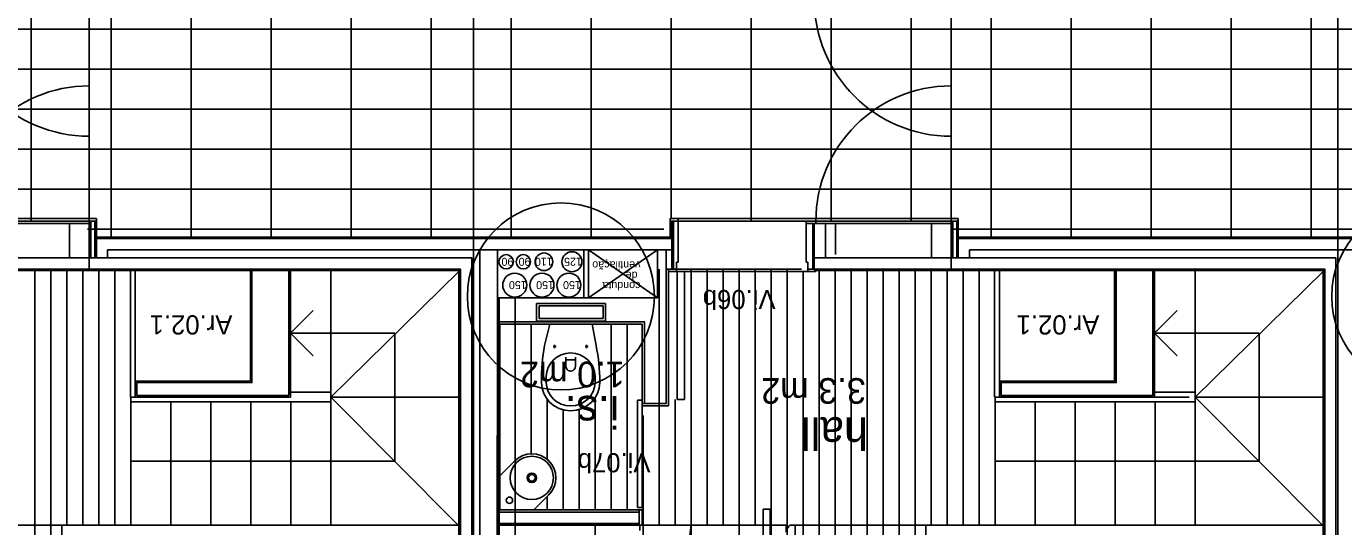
# Model space of a CAD drawing. Extents: x 1248 to 1356, y -443 to -224.
# Drawn here: x 1326.49 to 1334.72, y -242.03 to -238.91 of the extents above; entities that cross this region are included whole.
import ezdxf

# ---------------------------------------------------------------- set-up
doc = ezdxf.new("R2010")
doc.units = 0
for name, color, linetype in [('corte', 7, 'Continuous'), ('estereoctomias', 7, 'Continuous'), ('ind-pormenores', 7, 'Continuous'), ('Level 1', 7, 'Continuous'), ('Level 10', 7, 'Continuous'), ('Level 11', 7, 'Continuous'), ('Level 13', 7, 'Continuous'), ('Level 2', 7, 'Continuous'), ('Level 31', 7, 'Continuous'), ('Level 4', 7, 'Continuous'), ('Level 40', 7, 'Continuous'), ('Level 41', 7, 'Continuous'), ('Level 60', 7, 'Continuous'), ('mob-fixo', 7, 'Continuous'), ('revestimentos', 7, 'Continuous'), ('vermelhos-cont', 7, 'Continuous')]:
    doc.layers.add(name, color=color, linetype=linetype)

msp = doc.modelspace()

# ---------------------------------------------------------------- linework, layer by layer
at = {"layer": 'corte'}
for p, q in [((1326.0968, -240.354), (1326.9268, -240.354)), ((1326.9968, -240.304), (1330.4325, -240.304)), ((1326.9968, -240.354), (1329.2718, -240.354)), ((1329.9725, -240.604), (1329.9725, -240.304)), ((1330.0025, -240.604), (1330.0025, -240.304)), ((1330.4325, -240.304), (1330.4325, -240.604)), ((1330.4875, -240.304), (1330.5225, -240.304)), ((1332.3125, -240.354), (1331.4825, -240.354)), ((1335.8333, -240.304), (1332.3825, -240.304)), ((1334.6725, -240.354), (1332.3825, -240.354)), ((1329.2018, -240.424), (1326.0268, -240.424)), ((1329.2018, -240.424), (1329.2018, -240.954)), ((1334.6025, -240.424), (1331.4125, -240.424)), ((1334.6025, -240.424), (1333.5289, -240.424)), ((1334.6025, -240.424), (1334.6025, -240.954)), ((1329.4325, -240.754), (1330.3525, -240.754))]:
    msp.add_line(p, q, dxfattribs=at)
at = {"layer": 'estereoctomias'}
msp.add_line((1330.5625, -240.124), (1331.3625, -240.124), dxfattribs=at)
for points in [[(1331.4825, -240.139), (1331.4825, -240.354), (1331.4125, -240.354), (1331.4125, -240.139)], [(1330.5225, -240.234), (1330.5225, -240.304), (1330.0025, -240.304), (1330.0025, -240.604), (1329.9725, -240.604), (1329.9725, -240.304), (1326.9968, -240.304), (1326.9968, -240.354), (1326.9268, -240.354), (1326.9268, -240.234)], [(1335.9383, -240.234), (1335.9383, -240.304), (1332.3825, -240.304), (1332.3825, -240.354), (1332.3125, -240.354), (1332.3125, -240.234)], [(1326.0268, -240.354), (1326.0268, -240.424), (1329.2018, -240.424), (1329.2018, -242.1713), (1329.2718, -242.1713), (1329.2718, -240.354), (1326.0268, -240.354)], [(1329.3225, -242.1713), (1329.4318, -242.1713), (1329.4325, -240.754), (1330.3525, -240.754), (1330.3525, -241.264), (1330.4875, -241.264), (1330.4875, -240.304), (1330.4325, -240.304), (1330.4325, -240.604), (1329.4325, -240.604), (1329.4325, -240.304), (1329.3225, -240.304)], [(1330.5225, -240.424), (1330.4875, -240.424), (1330.4875, -240.314), (1330.4875, -240.304), (1330.5225, -240.304), (1330.5225, -240.314)], [(1334.6725, -240.354), (1334.6725, -242.1713), (1334.6025, -242.1713), (1334.6025, -240.424), (1331.4125, -240.424), (1331.4125, -240.354)], [(1328.1289, -240.424), (1328.1289, -241.214), (1327.1789, -241.214), (1327.1789, -241.134), (1327.8989, -241.134), (1327.8989, -240.424)], [(1333.5296, -240.424), (1333.5296, -241.214), (1332.5796, -241.214), (1332.5796, -241.134), (1333.2996, -241.134), (1333.2996, -240.424)], [(1330.3175, -241.944), (1330.3175, -242.014), (1329.4325, -242.014), (1329.4325, -241.944)]]:
    msp.add_lwpolyline(points, close=True, dxfattribs=at)
at = {"layer": 'ind-pormenores'}
for centre in [(1329.8293, -240.5951), (1335.2301, -240.5951)]:
    msp.add_circle(centre, 0.5842, dxfattribs=at)
at = {"layer": 'Level 1'}
for p, q in [((1331.4825, -240.139), (1331.4125, -240.139)), ((1331.4125, -240.424), (1331.4125, -240.139)), ((1331.4825, -240.354), (1331.4825, -240.139)), ((1326.9268, -240.234), (1330.5225, -240.234)), ((1326.9268, -240.234), (1326.9268, -240.354)), ((1330.5225, -240.424), (1330.5225, -240.234)), ((1332.3125, -240.234), (1335.9383, -240.234)), ((1332.3125, -240.234), (1332.3125, -240.354)), ((1326.9968, -240.304), (1326.9968, -240.354)), ((1329.2718, -240.354), (1329.2718, -245.8713)), ((1329.3225, -240.304), (1329.3225, -246.734)), ((1329.4325, -241.934), (1329.4325, -240.304)), ((1330.4875, -241.264), (1330.4875, -240.304)), ((1332.3825, -240.304), (1332.3825, -240.354)), ((1334.6725, -240.354), (1334.6725, -245.8713)), ((1327.8989, -240.424), (1327.8989, -241.134)), ((1328.1289, -241.214), (1328.1289, -240.424)), ((1329.2018, -240.424), (1329.2018, -246.584)), ((1329.2018, -246.584), (1329.2018, -240.424)), ((1330.5225, -240.424), (1330.4875, -240.424)), ((1333.2989, -240.424), (1333.2989, -241.134)), ((1333.5289, -241.214), (1333.5289, -240.424)), ((1334.6025, -240.424), (1334.6025, -246.584)), ((1334.6025, -246.584), (1334.6025, -240.424)), ((1329.4325, -240.604), (1330.4325, -240.604)), ((1330.3525, -240.754), (1330.3525, -241.264)), ((1327.8989, -241.134), (1327.1789, -241.134)), ((1327.1789, -241.134), (1327.1789, -241.214)), ((1333.2989, -241.134), (1332.5789, -241.134)), ((1332.5789, -241.134), (1332.5789, -241.214)), ((1327.1789, -241.214), (1328.1289, -241.214)), ((1332.5789, -241.214), (1333.5289, -241.214)), ((1330.3375, -241.264), (1330.4875, -241.264)), ((1329.4325, -246.584), (1329.4325, -241.934)), ((1330.3175, -241.944), (1329.4325, -241.944)), ((1330.3175, -242.024), (1330.3175, -241.929)), ((1329.4325, -242.014), (1330.3175, -242.014))]:
    msp.add_line(p, q, dxfattribs=at)
at = {"layer": 'Level 10'}
for p, q in [((1327.0183, -238.624), (1327.0183, -240.224)), ((1327.5183, -238.624), (1327.5183, -240.224)), ((1328.0183, -238.624), (1328.0183, -240.224)), ((1328.5183, -238.624), (1328.5183, -240.224)), ((1329.0183, -238.624), (1329.0183, -240.224)), ((1329.5183, -238.624), (1329.5183, -240.224)), ((1330.0183, -238.624), (1330.0183, -240.224)), ((1332.5183, -238.624), (1332.5183, -240.224)), ((1333.0183, -238.624), (1333.0183, -240.224)), ((1333.5183, -238.624), (1333.5183, -240.224)), ((1334.0183, -238.624), (1334.0183, -240.224)), ((1334.5183, -238.624), (1334.5183, -240.224)), ((1326.5183, -238.724), (1326.5183, -240.124)), ((1330.5183, -238.739), (1330.5183, -240.109)), ((1331.0183, -238.724), (1331.0183, -240.124)), ((1331.5183, -238.724), (1331.5183, -240.124)), ((1332.0183, -238.724), (1332.0183, -240.124)), ((1348.9433, -238.924), (1315.7644, -238.924)), ((1347.9933, -239.174), (1315.7633, -239.174)), ((1347.9933, -239.424), (1315.7633, -239.424)), ((1347.9933, -239.674), (1315.7633, -239.674)), ((1347.9933, -239.924), (1315.7633, -239.924)), ((1330.4725, -240.174), (1326.8718, -240.174)), ((1335.8733, -240.174), (1332.2725, -240.174)), ((1330.4425, -240.424), (1330.4425, -242.024)), ((1330.5125, -240.424), (1331.3325, -240.424)), ((1330.6425, -240.424), (1330.6425, -242.024)), ((1330.7425, -240.424), (1330.7425, -242.024)), ((1330.8425, -240.424), (1330.8425, -242.024)), ((1330.9425, -240.424), (1330.9425, -242.024)), ((1331.0425, -240.424), (1331.0425, -242.024)), ((1331.1425, -240.424), (1331.1425, -242.892)), ((1331.2425, -240.424), (1331.2425, -242.892)), ((1331.4425, -240.434), (1331.4425, -242.892)), ((1331.5425, -240.434), (1331.5425, -246.574)), ((1331.6425, -240.434), (1331.6425, -246.574)), ((1331.7425, -240.434), (1331.7425, -246.574)), ((1331.8425, -240.434), (1331.8425, -246.574)), ((1331.9425, -240.434), (1331.9425, -246.574)), ((1332.0425, -240.434), (1332.0425, -246.574)), ((1332.1425, -240.434), (1332.1425, -242.024)), ((1332.2425, -240.434), (1332.2425, -242.024)), ((1332.3425, -240.434), (1332.3425, -242.024)), ((1332.4425, -240.434), (1332.4425, -242.024)), ((1326.5418, -240.439), (1326.5418, -246.574)), ((1326.6418, -240.439), (1326.6418, -246.574)), ((1326.7418, -240.439), (1326.7418, -242.024)), ((1326.8418, -240.439), (1326.8418, -242.024)), ((1326.9418, -240.439), (1326.9418, -242.024)), ((1327.0418, -240.439), (1327.0418, -242.024)), ((1331.3425, -240.439), (1331.3425, -242.892)), ((1329.5425, -240.769), (1329.5425, -241.6218)), ((1329.6425, -240.769), (1329.6425, -241.579)), ((1330.1425, -240.769), (1330.1425, -241.929)), ((1330.2425, -240.769), (1330.2425, -241.929)), ((1329.7425, -241.2366), (1329.7425, -241.6129)), ((1330.0425, -241.2297), (1330.0425, -241.929)), ((1330.5425, -241.239), (1330.5425, -242.024)), ((1329.8425, -241.3035), (1329.8425, -241.929)), ((1329.9425, -241.3022), (1329.9425, -241.929)), ((1330.3425, -241.339), (1330.3425, -242.024)), ((1329.7425, -241.8461), (1329.7425, -241.929)), ((1330.3375, -242.024), (1331.0925, -242.024)), ((1330.3425, -244.428), (1330.3425, -242.024)), ((1330.6425, -244.428), (1330.6425, -242.024)), ((1330.9425, -244.428), (1330.9425, -242.024))]:
    msp.add_line(p, q, dxfattribs=at)
at = {"layer": 'Level 11'}
for p, q in [((1329.6775, -240.749), (1329.6775, -240.639)), ((1330.1075, -240.639), (1329.6775, -240.639)), ((1330.0925, -240.654), (1329.6925, -240.654)), ((1329.6925, -240.734), (1329.6925, -240.654)), ((1330.0925, -240.734), (1330.0925, -240.654)), ((1330.1075, -240.749), (1330.1075, -240.639)), ((1330.1075, -240.749), (1329.6775, -240.749)), ((1330.0925, -240.734), (1329.6925, -240.734)), ((1329.7602, -240.769), (1329.7261, -240.9017)), ((1329.7602, -240.769), (1330.0248, -240.769)), ((1330.0248, -240.769), (1330.049, -240.9017)), ((1329.7801, -240.9078), (1329.8001, -240.9078)), ((1329.7901, -240.8978), (1329.7901, -240.9178)), ((1329.9801, -240.9078), (1330.0001, -240.9078)), ((1329.9901, -240.8978), (1329.9901, -240.9178)), ((1329.8601, -240.9742), (1329.8601, -241.0313)), ((1329.8601, -240.9919), (1329.9201, -240.9919)), ((1329.9201, -240.9742), (1329.9201, -241.0314)), ((1329.7376, -241.1322), (1329.7376, -241.0961)), ((1330.0426, -241.1322), (1330.0426, -241.0961)), ((1329.7076, -241.1288), (1329.7076, -241.1325)), ((1330.0726, -241.1288), (1330.0726, -241.1325)), ((1329.5414, -241.6229), (1329.4475, -241.7168)), ((1329.4475, -241.7168), (1329.4475, -241.929)), ((1329.7536, -241.835), (1329.6597, -241.929)), ((1329.4475, -241.929), (1329.6597, -241.929))]:
    msp.add_line(p, q, dxfattribs=at)
for centre, radius in [((1329.6475, -241.729), 0.135), ((1329.6475, -241.729), 0.03), ((1329.6475, -241.729), 0.02), ((1329.5075, -241.869), 0.02)]:
    msp.add_circle(centre, radius, dxfattribs=at)
for centre, radius, start, end in [((1329.8901, -241.0312), 0.03, 179.99953, 0.00125), ((1329.6475, -241.729), 0.15, 314.99996, 134.99979)]:
    msp.add_arc(centre, radius, start, end, dxfattribs=at)
for centre, major_axis, ratio, start_param, end_param in [((1331.1071, -241.1288), (0, -1.4), 0.999692, 4.549473, 4.712392), ((1328.2942, -241.1288), (1.7783, 0), 0.787256, 6.283184, 6.446103), ((1329.8901, -241.0961), (0.1525, 0), 0.967187, 0.000003, 3.14159), ((1329.8901, -241.1322), (0.1825, 0), 0.972581, 3.141597, 6.283184), ((1329.8901, -241.1322), (0.1525, 0), 0.967187, 3.141597, 6.283184)]:
    msp.add_ellipse(centre, major_axis=major_axis, ratio=ratio, start_param=start_param, end_param=end_param, dxfattribs=at)
at = {"layer": 'Level 13'}
for p, q in [((1326.8818, -240.124), (1326.8818, -240.109)), ((1326.8818, -240.109), (1326.9268, -240.109)), ((1326.9268, -240.124), (1326.9268, -240.109)), ((1330.5625, -240.109), (1330.5125, -240.109)), ((1330.5125, -240.109), (1330.5125, -240.224)), ((1330.5625, -240.124), (1330.5625, -240.109)), ((1332.2675, -240.124), (1332.2675, -240.109)), ((1332.2675, -240.109), (1332.3125, -240.109)), ((1332.3125, -240.124), (1332.3125, -240.109)), ((1326.8818, -240.139), (1325.9768, -240.139)), ((1326.8818, -240.124), (1326.0168, -240.124)), ((1326.8818, -240.124), (1326.0168, -240.124)), ((1326.8818, -240.124), (1326.0368, -240.124)), ((1326.8818, -240.139), (1326.8818, -240.124)), ((1326.8818, -240.124), (1326.9268, -240.124)), ((1326.8818, -240.139), (1326.8818, -240.354)), ((1326.8918, -240.124), (1326.8918, -240.354)), ((1326.9168, -240.124), (1326.9168, -240.354)), ((1326.9268, -240.144), (1326.9268, -240.124)), ((1326.9268, -240.144), (1326.9268, -240.354)), ((1330.5125, -240.124), (1330.5625, -240.124)), ((1330.5225, -240.244), (1330.5225, -240.124)), ((1330.5325, -240.424), (1330.5325, -240.124)), ((1330.5625, -240.38), (1330.5625, -240.124)), ((1331.3625, -240.139), (1331.3625, -240.124)), ((1331.4225, -240.124), (1331.3625, -240.124)), ((1331.3625, -240.139), (1331.3625, -240.38)), ((1332.2675, -240.139), (1331.3625, -240.139)), ((1332.2675, -240.124), (1331.4025, -240.124)), ((1332.2675, -240.124), (1331.4025, -240.124)), ((1331.4025, -240.424), (1331.4025, -240.139)), ((1332.2675, -240.124), (1331.4225, -240.124)), ((1331.4225, -240.139), (1331.4225, -240.124)), ((1332.2675, -240.139), (1332.2675, -240.124)), ((1332.2675, -240.124), (1332.3125, -240.124)), ((1332.2675, -240.139), (1332.2675, -240.354)), ((1332.2775, -240.124), (1332.2775, -240.354)), ((1332.3025, -240.124), (1332.3025, -240.354)), ((1332.3125, -240.144), (1332.3125, -240.124)), ((1332.3125, -240.144), (1332.3125, -240.354)), ((1330.5325, -240.424), (1330.5325, -240.224)), ((1327.1689, -241.224), (1327.1689, -240.424)), ((1330.5025, -241.279), (1330.5025, -240.424)), ((1330.5625, -240.38), (1330.5525, -240.38)), ((1330.5525, -240.424), (1330.5525, -240.38)), ((1331.3625, -240.38), (1331.3725, -240.38)), ((1331.3725, -240.424), (1331.3725, -240.38)), ((1332.5389, -241.224), (1332.5389, -240.434)), ((1332.5689, -241.224), (1332.5689, -240.434)), ((1327.1389, -241.224), (1327.1389, -240.439)), ((1330.5565, -240.439), (1330.5565, -241.239)), ((1330.5575, -240.439), (1330.6015, -240.439)), ((1330.6015, -240.439), (1330.6015, -241.239)), ((1327.1689, -241.224), (1327.1389, -241.224)), ((1330.3075, -241.244), (1330.3075, -241.914)), ((1330.3075, -241.244), (1330.3375, -241.244)), ((1330.3375, -241.244), (1330.3375, -241.914)), ((1330.6015, -241.239), (1330.5565, -241.239)), ((1332.5689, -241.224), (1332.5389, -241.224)), ((1330.5025, -241.279), (1330.3375, -241.279)), ((1330.3375, -241.914), (1330.3075, -241.914)), ((1331.1375, -241.924), (1331.0925, -241.924)), ((1331.0925, -242.819), (1331.0925, -241.924)), ((1331.1375, -242.819), (1331.1375, -241.924)), ((1331.1375, -242.819), (1331.1375, -241.924)), ((1331.1375, -242.819), (1331.1375, -241.924)), ((1326.7098, -242.024), (1326.7098, -242.224)), ((1326.7098, -242.024), (1329.1918, -242.024)), ((1326.7098, -242.024), (1329.1918, -242.024)), ((1327.1383, -242.024), (1329.1918, -242.024)), ((1327.1418, -242.024), (1329.1874, -242.024)), ((1329.1118, -242.024), (1328.7426, -242.024)), ((1329.1118, -242.024), (1328.7426, -242.024)), ((1330.0425, -245.121), (1330.0425, -242.024)), ((1331.2925, -242.024), (1331.2675, -242.024)), ((1331.2925, -242.8898), (1331.2925, -242.024)), ((1332.1105, -242.024), (1332.1105, -242.224)), ((1332.1105, -242.024), (1334.5925, -242.024)), ((1332.1105, -242.024), (1334.5925, -242.024)), ((1332.5391, -242.024), (1334.5925, -242.024)), ((1332.5425, -242.024), (1334.5881, -242.024)), ((1334.5125, -242.024), (1334.1434, -242.024)), ((1334.5125, -242.024), (1334.1434, -242.024))]:
    msp.add_line(p, q, dxfattribs=at)
for points in [[(1330.5525, -240.424), (1330.5025, -240.424), (1330.5025, -240.439), (1330.5525, -240.439)], [(1331.4225, -240.439), (1331.3725, -240.439), (1331.3725, -240.424), (1331.4225, -240.424)]]:
    msp.add_lwpolyline(points, close=True, dxfattribs=at)
msp.add_arc((1331.2675, -242.044), 0.02, 90, 180, dxfattribs=at)
at = {"layer": 'Level 2'}
for p, q in [((1328.3918, -240.439), (1328.3918, -241.194)), ((1328.3918, -241.224), (1329.1918, -240.439)), ((1333.7925, -240.439), (1333.7925, -241.194)), ((1333.7925, -241.224), (1334.5925, -240.439)), ((1328.2803, -240.6826), (1328.1389, -240.824)), ((1333.6803, -240.6826), (1333.5389, -240.824)), ((1328.7918, -240.824), (1328.1389, -240.824)), ((1328.2803, -240.9654), (1328.1389, -240.824)), ((1328.7918, -240.824), (1328.7918, -241.624)), ((1333.6803, -240.9654), (1333.5389, -240.824)), ((1334.1925, -240.824), (1333.5425, -240.824)), ((1334.1925, -240.824), (1334.1925, -241.624)), ((1327.1418, -241.224), (1327.1418, -242.024)), ((1328.3918, -241.254), (1327.1418, -241.254)), ((1327.3918, -241.254), (1327.3918, -242.024)), ((1327.6418, -241.254), (1327.6418, -242.024)), ((1327.8918, -241.254), (1327.8918, -242.024)), ((1328.3918, -241.194), (1328.1389, -241.194)), ((1328.1418, -241.254), (1328.1418, -242.024)), ((1328.3918, -241.194), (1328.3918, -241.254)), ((1329.1918, -241.224), (1328.3918, -241.224)), ((1328.3918, -241.224), (1329.1874, -242.024)), ((1328.3918, -241.254), (1328.3918, -242.024)), ((1332.5425, -241.224), (1332.5425, -242.024)), ((1333.7925, -241.254), (1332.5425, -241.254)), ((1332.7925, -241.254), (1332.7925, -242.024)), ((1333.0425, -241.254), (1333.0425, -242.024)), ((1333.2925, -241.254), (1333.2925, -242.024)), ((1333.7925, -241.194), (1333.5389, -241.194)), ((1333.7561, -241.224), (1333.5389, -241.224)), ((1333.5425, -241.254), (1333.5425, -242.024)), ((1333.7925, -241.194), (1333.7925, -241.254)), ((1334.5925, -241.224), (1333.7925, -241.224)), ((1333.7925, -241.224), (1334.5881, -242.024)), ((1333.7925, -241.254), (1333.7925, -242.024)), ((1327.1418, -241.624), (1328.7918, -241.624)), ((1332.5425, -241.624), (1334.1925, -241.624))]:
    msp.add_line(p, q, dxfattribs=at)
at = {"layer": 'Level 31'}
for p, q in [((1330.3375, -241.929), (1330.3175, -241.929)), ((1330.3375, -242.024), (1330.3375, -241.929)), ((1330.3375, -242.024), (1330.3175, -242.024))]:
    msp.add_line(p, q, dxfattribs=at)
at = {"layer": 'Level 4'}
for p, q in [((1326.8818, -238.724), (1326.8818, -239.5941)), ((1332.2675, -238.724), (1332.2675, -239.5941)), ((1326.8818, -240.124), (1326.8818, -239.279)), ((1332.2675, -240.124), (1332.2675, -239.279)), ((1325.1768, -240.109), (1326.8818, -240.109)), ((1330.5625, -240.109), (1332.2675, -240.109)), ((1326.7593, -240.354), (1326.7593, -240.139)), ((1331.545, -240.334), (1331.545, -240.139)), ((1332.145, -240.354), (1332.145, -240.139)), ((1326.8818, -240.354), (1326.8818, -240.424)), ((1332.2675, -240.354), (1332.2675, -240.424)), ((1331.3725, -240.439), (1330.6015, -240.439)), ((1325.8918, -242.024), (1326.7098, -242.024)), ((1329.4425, -242.024), (1330.0425, -242.024)), ((1330.3225, -242.059), (1330.3225, -242.024)), ((1331.2375, -242.024), (1330.3225, -242.024)), ((1331.2375, -242.069), (1331.2375, -242.024)), ((1331.2925, -242.024), (1332.1105, -242.024))]:
    msp.add_line(p, q, dxfattribs=at)
for centre in [(1326.8818, -240.124), (1332.2675, -240.124)]:
    msp.add_arc(centre, 0.845, 90, 180, dxfattribs=at)
for centre, major_axis, ratio, end_param in [((1326.8818, -238.739), (-0.8551, 0), 0.999998, 1.570796), ((1332.2675, -238.739), (-0.8551, 0), 0.999998, 1.570796), ((1330.0425, -241.9731), (0, -0.6509), 0.924693, 1.492592)]:
    msp.add_ellipse(centre, major_axis=major_axis, ratio=ratio, start_param=0, end_param=end_param, dxfattribs=at)
at = {"layer": 'Level 41'}
for p, q in [((1330.4325, -240.604), (1330.0025, -240.304)), ((1330.0025, -240.604), (1330.4325, -240.304))]:
    msp.add_line(p, q, dxfattribs=at)
for centre, radius in [((1329.4873, -240.3785), 0.045), ((1329.5944, -240.3785), 0.045), ((1329.7233, -240.3785), 0.055), ((1329.8982, -240.3785), 0.0625), ((1329.5408, -240.5244), 0.075), ((1329.711, -240.5244), 0.075), ((1329.8791, -240.5244), 0.075)]:
    msp.add_circle(centre, radius, dxfattribs=at)
at = {"layer": 'mob-fixo'}
for p, q in [((1329.4425, -244.091), (1329.4425, -240.604)), ((1329.5425, -244.091), (1329.5425, -240.604))]:
    msp.add_line(p, q, dxfattribs=at)
at = {"layer": 'revestimentos'}
for p, q in [((1326.9268, -240.224), (1330.5225, -240.224)), ((1332.3125, -240.224), (1335.9383, -240.224)), ((1329.1918, -240.434), (1326.0268, -240.434)), ((1327.8889, -240.424), (1327.8889, -241.124)), ((1328.1389, -241.224), (1328.1389, -240.424)), ((1329.1918, -246.574), (1329.1918, -240.424)), ((1329.1918, -246.574), (1329.1918, -240.424)), ((1334.5925, -240.434), (1331.4125, -240.434)), ((1333.2889, -240.434), (1333.2889, -241.124)), ((1333.5389, -241.224), (1333.5389, -240.434)), ((1334.5925, -240.434), (1333.5389, -240.434)), ((1334.5925, -246.574), (1334.5925, -240.424)), ((1334.5925, -246.574), (1334.5925, -240.434)), ((1329.4475, -241.929), (1329.4475, -240.769)), ((1329.4475, -240.769), (1330.3375, -240.769)), ((1330.3375, -240.769), (1330.3375, -241.264)), ((1327.8889, -241.124), (1327.1689, -241.124)), ((1327.1689, -241.124), (1327.1689, -241.224)), ((1333.2889, -241.124), (1332.5689, -241.124)), ((1332.5689, -241.124), (1332.5689, -241.224)), ((1327.1689, -241.224), (1328.1389, -241.224)), ((1332.5689, -241.224), (1333.5389, -241.224)), ((1330.3175, -241.929), (1329.4475, -241.929)), ((1329.4425, -246.574), (1329.4425, -242.024)), ((1329.4425, -242.024), (1330.3175, -242.024))]:
    msp.add_line(p, q, dxfattribs=at)
at = {"layer": 'vermelhos-cont'}
for p, q in [((1329.284, -250.7923), (1329.284, -229.6198)), ((1334.684, -250.7923), (1334.684, -229.6198))]:
    msp.add_line(p, q, dxfattribs=at)

# ---------------------------------------------------------------- texts
at = {"layer": 'Level 40'}
for s, p in [('Vi.06b', (1331.1708, -240.5543)), ('Ar.02.1', (1327.7767, -240.7128)), ('Ar.02.1', (1333.1939, -240.7128)), ('Vi.07b', (1330.389, -241.5742))]:
    msp.add_text(s, height=0.12, rotation=180.00001, dxfattribs=at).set_placement(p)
at = {"layer": 'Level 41'}
for s, p in [('90', (1329.5323, -240.3535)), ('90', (1329.6394, -240.3535)), ('110', (1329.7783, -240.3535)), ('125', (1329.9607, -240.3535)), ('ventilação ', (1330.3265, -240.3755)), ('150', (1329.6158, -240.4994)), ('150', (1329.786, -240.4994)), ('150', (1329.9541, -240.4994)), ('conduta', (1330.3265, -240.5044)), (' de ', (1330.3265, -240.4399))]:
    msp.add_text(s, height=0.05, rotation=180, dxfattribs=at).set_placement(p)
at = {"layer": 'Level 60'}
for s, height, p in [('1.0 m2', 0.16, (1330.228, -241.0026)), ('3.3 m2', 0.16, (1331.7349, -241.1056)), ('i.s.', 0.2, (1330.1941, -241.2167)), ('hall', 0.2, (1331.7471, -241.3499))]:
    msp.add_text(s, height=height, rotation=180, dxfattribs=at).set_placement(p)

doc.saveas('drawing.dxf')
